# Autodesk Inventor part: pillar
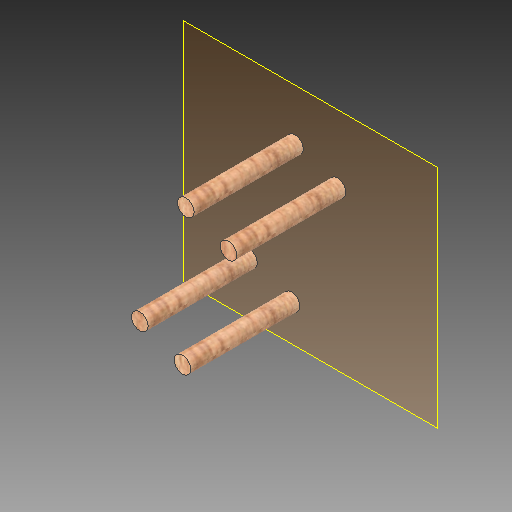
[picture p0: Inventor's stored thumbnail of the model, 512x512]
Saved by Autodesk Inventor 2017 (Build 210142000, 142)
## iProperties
Created: 2017-05
Part Number: pillar
Material: Wood (Birch)
Document SubType Name: Modeling
Designer: 1717440
Density: 0.55 g/cm^3
Appearance: Birch - Natural Polished
Author: 1717440
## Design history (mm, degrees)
workplane "Work Plane1"
sketch "Sketch1"
  geometry: C1 r 6.425 at (39.674, 12.092) reference; C2 r 6.425 at (6.931, 24.456) reference; C3 r 6.425 at (-28.395, -69.097) reference; C4 r 6.425 at (4.348, -81.461) reference; C5 r 6.35 at (6.931, 24.456); C6 r 6.35 at (39.674, 12.092); C7 r 6.35 at (-28.395, -69.097); C8 r 6.35 at (4.348, -81.461); 1 further point
  constraints: 4 centre point, 4 coincident
  dimensions: "d0" = 12.7 diameter of C5; "d1" = 12.7 diameter of C6; "d2" = 12.7 diameter of C7; "d3" = 12.7 diameter of C8
  node "Reference1"
  node "Reference2"
  node "Reference3"
  node "Reference4"
workplane "Work Plane2"
extrude "Extrusion1" new body sketch "Sketch1" stored distance "d4" = 10; taper "d5" = 0 deg
body "Solid1"
